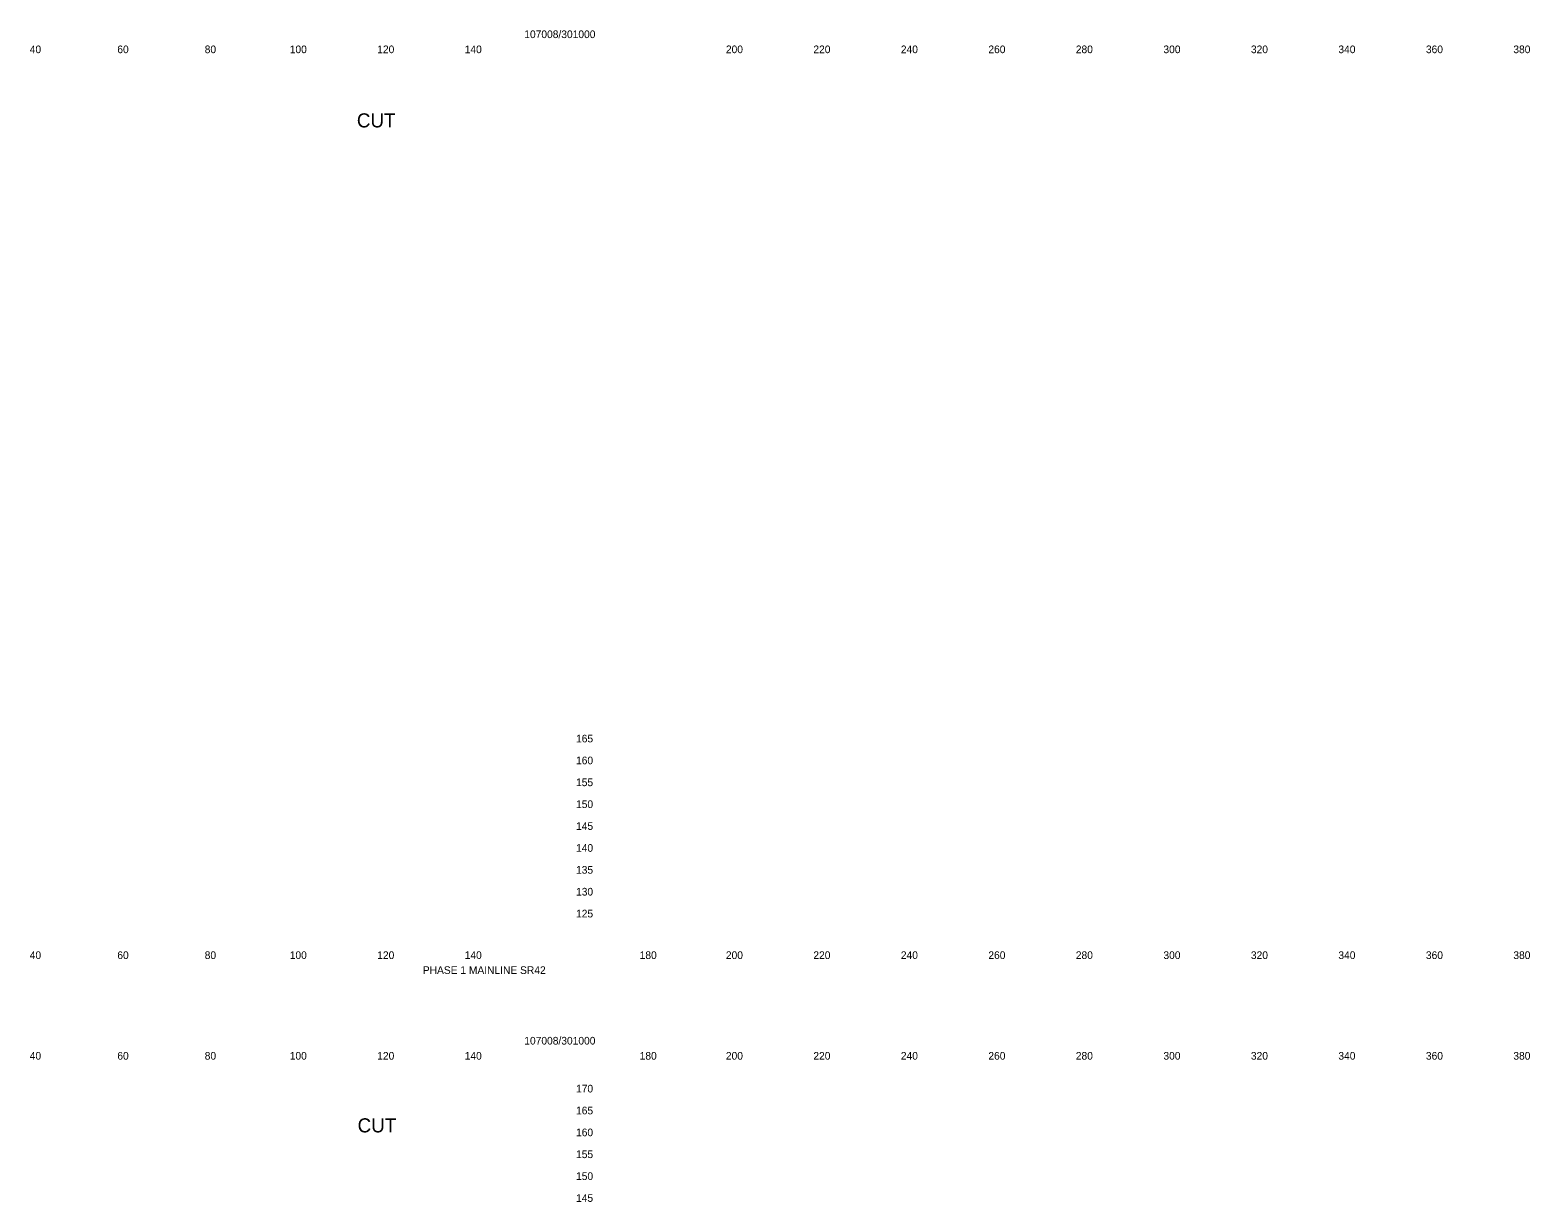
# Model space of a CAD drawing. Extents: x 21281 to 22024, y 6472 to 15198.
# Drawn here: x 21681.3 to 22024.2, y 14929.8 to 15197.6 of the extents above; entities that cross this region are included whole.
import ezdxf

# ---------------------------------------------------------------- set-up
doc = ezdxf.new("R2010")
doc.units = 0
doc.layers.add('XS_SHEET_LABELS_ELEVATION', color=7, linetype='Continuous')
doc.layers.add('XS_SHEET_LABELS_OFFSET', color=7, linetype='Continuous')

msp = doc.modelspace()

# ---------------------------------------------------------------- texts
at = {"layer": 'XS_SHEET_LABELS_ELEVATION'}
for s, p in [('  165  ', (21804.84, 15034.84)), ('  160  ', (21804.84, 15029.84)), ('  155  ', (21804.84, 15024.84)), ('  150  ', (21804.84, 15019.84)), ('  145  ', (21804.84, 15014.84)), ('  140  ', (21804.84, 15009.84)), ('  135  ', (21804.84, 15004.84)), ('  130  ', (21804.84, 14999.84)), ('  125  ', (21804.84, 14994.84)), ('  170  ', (21804.84, 14954.84)), ('  165  ', (21804.84, 14949.84)), ('  160  ', (21804.84, 14944.84)), ('  155  ', (21804.84, 14939.84)), ('  150  ', (21804.84, 14934.84)), ('  145  ', (21804.84, 14929.84))]:
    msp.add_text(s, height=1.75, dxfattribs=at).set_placement(p)
at = {"layer": 'XS_SHEET_LABELS_OFFSET'}
for s, height, p in [('107008/301000', 1.75, (21794.31, 15195.79)), ('  40  ', 1.75, (21679.95, 15192.34)), ('  60  ', 1.75, (21699.97, 15192.34)), ('  80  ', 1.75, (21719.95, 15192.34)), ('  100  ', 1.75, (21739.39, 15192.34)), ('  120  ', 1.75, (21759.39, 15192.34)), ('  140  ', 1.75, (21779.39, 15192.34)), ('  200  ', 1.75, (21839.1, 15192.34)), ('  220  ', 1.75, (21859.1, 15192.34)), ('  240  ', 1.75, (21879.1, 15192.34)), ('  260  ', 1.75, (21899.11, 15192.34)), ('  280  ', 1.75, (21919.1, 15192.34)), ('  300  ', 1.75, (21939.13, 15192.34)), ('  320  ', 1.75, (21959.13, 15192.34)), ('  340  ', 1.75, (21979.13, 15192.34)), ('  360  ', 1.75, (21999.14, 15192.34)), ('  380  ', 1.75, (22019.13, 15192.34)), ('CUT', 3.222, (21756.03, 15175.37)), ('  40  ', 1.75, (21679.95, 14985.34)), ('  60  ', 1.75, (21699.97, 14985.34)), ('  80  ', 1.75, (21719.95, 14985.34)), ('  100  ', 1.75, (21739.39, 14985.34)), ('  120  ', 1.75, (21759.39, 14985.34)), ('  140  ', 1.75, (21779.39, 14985.34)), ('  180  ', 1.75, (21819.39, 14985.34)), ('  200  ', 1.75, (21839.1, 14985.34)), ('  220  ', 1.75, (21859.1, 14985.34)), ('  240  ', 1.75, (21879.1, 14985.34)), ('  260  ', 1.75, (21899.11, 14985.34)), ('  280  ', 1.75, (21919.1, 14985.34)), ('  300  ', 1.75, (21939.13, 14985.34)), ('  320  ', 1.75, (21959.13, 14985.34)), ('  340  ', 1.75, (21979.13, 14985.34)), ('  360  ', 1.75, (21999.14, 14985.34)), ('  380  ', 1.75, (22019.13, 14985.34)), ('PHASE 1 MAINLINE SR42', 1.75, (21771.11, 14981.92)), ('107008/301000', 1.75, (21794.31, 14965.79)), ('  40  ', 1.75, (21679.95, 14962.34)), ('  60  ', 1.75, (21699.97, 14962.34)), ('  80  ', 1.75, (21719.95, 14962.34)), ('  100  ', 1.75, (21739.39, 14962.34)), ('  120  ', 1.75, (21759.39, 14962.34)), ('  140  ', 1.75, (21779.39, 14962.34)), ('  180  ', 1.75, (21819.39, 14962.34)), ('  200  ', 1.75, (21839.1, 14962.34)), ('  220  ', 1.75, (21859.1, 14962.34)), ('  240  ', 1.75, (21879.1, 14962.34)), ('  260  ', 1.75, (21899.11, 14962.34)), ('  280  ', 1.75, (21919.1, 14962.34)), ('  300  ', 1.75, (21939.13, 14962.34)), ('  320  ', 1.75, (21959.13, 14962.34)), ('  340  ', 1.75, (21979.13, 14962.34)), ('  360  ', 1.75, (21999.14, 14962.34)), ('  380  ', 1.75, (22019.13, 14962.34)), ('CUT', 3.222, (21756.2, 14945.71))]:
    msp.add_text(s, height=height, dxfattribs=at).set_placement(p)

doc.saveas('drawing.dxf')
